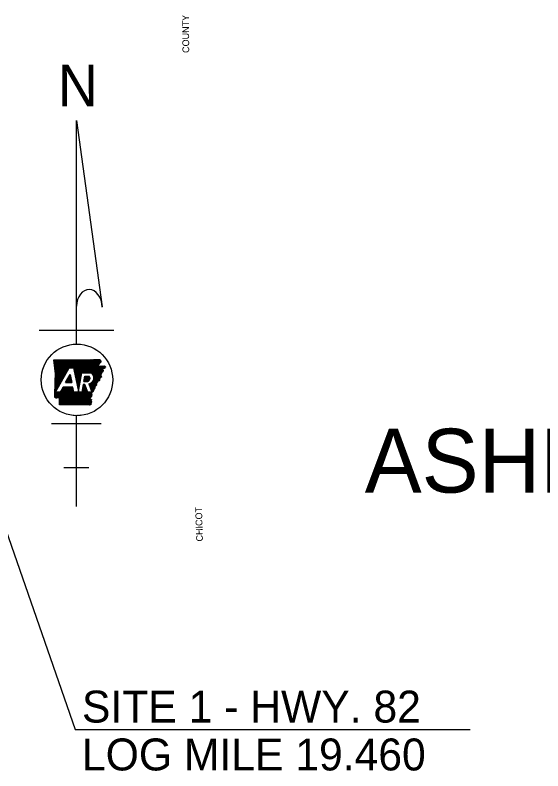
# Model space of a CAD drawing. Extents: x -2512 to 3792, y -435 to 2624.
# Drawn here: x 953 to 1350, y 1338 to 1907 of the extents above; entities that cross this region are included whole.
import ezdxf

# ---------------------------------------------------------------- set-up
doc = ezdxf.new("R2010")
doc.units = 0
for name, color, linetype in [('2', 7, 'Continuous'), ('Level 30', 7, 'Continuous'), ('R_Annotation', 7, 'Continuous'), ('R_Draft', 7, 'Continuous')]:
    doc.layers.add(name, color=color, linetype=linetype)

msp = doc.modelspace()

# ---------------------------------------------------------------- linework, layer by layer
at = {"layer": 'R_Annotation'}
for p, q in [((898.98, 1653.09), (997.83, 1369.55)), ((997.83, 1369.55), (1295.07, 1369.55))]:
    msp.add_line(p, q, dxfattribs=at)
at = {"layer": 'R_Draft'}
for p, q in [((998.69, 1827.36), (1018.1, 1687.13)), ((998.69, 1659.2), (998.69, 1827.36)), ((970.61, 1669.59), (1026.77, 1669.59)), ((981.66, 1647.15), (981.89, 1647.38)), ((981.74, 1646.49), (982.63, 1647.38)), ((981.82, 1645.83), (983.37, 1647.38)), ((981.9, 1645.17), (984.12, 1647.38)), ((981.99, 1644.5), (984.86, 1647.38)), ((982.07, 1643.84), (985.6, 1647.38)), ((982.15, 1643.18), (986.35, 1647.38)), ((982.23, 1642.52), (987.09, 1647.38)), ((982.31, 1641.86), (987.83, 1647.38)), ((982.4, 1641.2), (988.57, 1647.38)), ((982.48, 1640.54), (989.32, 1647.38)), ((982.56, 1639.88), (990.06, 1647.38)), ((982.64, 1639.22), (990.8, 1647.38)), ((982.73, 1638.56), (991.55, 1647.37)), ((982.75, 1631.15), (998.99, 1647.39)), ((982.78, 1631.92), (998.25, 1647.39)), ((982.8, 1632.69), (997.5, 1647.39)), ((982.81, 1637.89), (992.29, 1647.38)), ((982.83, 1633.45), (996.76, 1647.38)), ((982.85, 1634.22), (996.01, 1647.38)), ((982.88, 1634.99), (995.27, 1647.38)), ((982.89, 1637.23), (993.03, 1647.38)), ((982.9, 1635.76), (994.52, 1647.38)), ((982.93, 1636.53), (993.78, 1647.38)), ((993.79, 1641.44), (999.74, 1647.39)), ((994.53, 1641.44), (1000.48, 1647.39)), ((995.28, 1641.44), (1001.23, 1647.4)), ((996.02, 1641.44), (1001.99, 1647.41)), ((996.48, 1641.16), (1002.74, 1647.42)), ((996.61, 1640.55), (1003.5, 1647.43)), ((996.74, 1639.94), (1004.25, 1647.45)), ((996.88, 1639.33), (1005.01, 1647.46)), ((997.01, 1638.71), (1005.76, 1647.47)), ((997.14, 1638.1), (1006.52, 1647.48)), ((997.27, 1637.49), (1007.27, 1647.49)), ((997.4, 1636.88), (1008.03, 1647.5)), ((997.53, 1636.26), (1008.78, 1647.52)), ((997.66, 1635.65), (1009.54, 1647.53)), ((997.79, 1635.04), (1010.29, 1647.54)), ((997.92, 1634.43), (1011.05, 1647.55)), ((998.06, 1633.81), (1011.81, 1647.57)), ((998.19, 1633.2), (1012.57, 1647.58)), ((1003.35, 1637.62), (1013.33, 1647.6)), ((1004.09, 1637.62), (1014.09, 1647.62)), ((1004.84, 1637.62), (1014.85, 1647.64)), ((1005.58, 1637.62), (1015.61, 1647.65)), ((1006.32, 1637.62), (1016.37, 1647.67)), ((1007.07, 1637.62), (1016.54, 1647.09)), ((1007.81, 1637.62), (1016.9, 1646.71)), ((1008.55, 1637.62), (1016.99, 1646.06)), ((1009.3, 1637.62), (1015.3, 1643.62)), ((1009.97, 1637.55), (1015.15, 1642.73)), ((1010.38, 1637.22), (1015.93, 1642.77)), ((1010.74, 1636.84), (1016.72, 1642.81)), ((1011.06, 1636.41), (1017.5, 1642.85)), ((1011.34, 1635.95), (1018.28, 1642.89)), ((1011.56, 1635.43), (1019.07, 1642.93)), ((1011.74, 1634.86), (1019.77, 1642.9)), ((1011.84, 1634.22), (1020.12, 1642.5)), ((982.67, 1628.84), (990.82, 1636.98)), ((982.7, 1629.61), (991.79, 1638.7)), ((982.73, 1630.38), (992.76, 1640.41)), ((982.97, 1623.13), (993.34, 1641.44)), ((993.34, 1641.44), (996.42, 1641.44)), ((998.32, 1632.59), (1002.54, 1636.81)), ((1002.68, 1637.62), (1009.88, 1637.62)), ((1011.04, 1631.19), (1016.72, 1636.87)), ((1011.69, 1632.58), (1018.43, 1639.32)), ((1011.84, 1633.48), (1018.35, 1639.98)), ((1017.6, 1637.75), (1018.52, 1638.67)), ((1019.79, 1641.43), (1020.47, 1642.1)), ((982.6, 1626.53), (987.9, 1631.84)), ((982.62, 1627.3), (988.87, 1633.55)), ((982.65, 1628.07), (989.84, 1635.27)), ((990.6, 1630.32), (993.99, 1636.31)), ((990.64, 1630.32), (994.46, 1634.14)), ((991.38, 1630.32), (994.59, 1633.53)), ((991.52, 1631.95), (994.32, 1634.75)), ((992.12, 1630.32), (994.72, 1632.91)), ((992.49, 1633.66), (994.19, 1635.36)), ((992.87, 1630.32), (994.85, 1632.3)), ((993.46, 1635.38), (994.06, 1635.97)), ((993.61, 1630.32), (994.98, 1631.69)), ((994.35, 1630.32), (995.11, 1631.08)), ((998.45, 1631.98), (1002.38, 1635.91)), ((998.58, 1631.37), (1002.22, 1635.01)), ((998.71, 1630.75), (1002.06, 1634.11)), ((998.84, 1630.14), (1001.91, 1633.21)), ((998.97, 1629.53), (1001.75, 1632.31)), ((999.1, 1628.92), (1001.59, 1631.41)), ((1004.24, 1631.13), (1008.16, 1635.04)), ((1004.24, 1631.13), (1007.33, 1631.13)), ((1004.4, 1632.02), (1007.41, 1635.04)), ((1004.55, 1632.92), (1006.67, 1635.04)), ((1004.71, 1633.82), (1005.93, 1635.04)), ((1004.87, 1634.72), (1005.18, 1635.04)), ((1004.92, 1635.04), (1008.3, 1635.04)), ((1004.99, 1631.13), (1008.57, 1634.71)), ((1005.73, 1631.13), (1008.82, 1634.22)), ((1006.47, 1631.13), (1008.96, 1633.61)), ((1007.22, 1631.13), (1008.89, 1632.8)), ((1008.62, 1628.02), (1016.86, 1636.26)), ((1008.82, 1627.48), (1017, 1635.66)), ((1009.02, 1626.94), (1017.14, 1635.05)), ((1009.22, 1626.39), (1017.27, 1634.45)), ((1014.73, 1631.17), (1015.78, 1632.21)), ((982.52, 1624.23), (984.99, 1626.7)), ((982.55, 1625), (985.96, 1628.41)), ((982.57, 1625.77), (986.93, 1630.13)), ((982.66, 1619.16), (990.47, 1626.97)), ((983.1, 1618.86), (991.21, 1626.97)), ((983.63, 1618.65), (991.96, 1626.97)), ((984.52, 1618.79), (992.7, 1626.97)), ((985.27, 1618.8), (993.44, 1626.97)), ((985.85, 1618.64), (994.19, 1626.97)), ((985.88, 1617.18), (995.67, 1626.97)), ((985.88, 1617.92), (994.93, 1626.97)), ((985.88, 1616.44), (996.06, 1626.62)), ((985.88, 1615.7), (996.2, 1626.01)), ((985.89, 1614.96), (996.33, 1625.4)), ((988.71, 1626.97), (986.53, 1623.13)), ((987.37, 1624.62), (989.73, 1626.97)), ((988.34, 1626.33), (988.98, 1626.97)), ((995.99, 1626.97), (988.71, 1626.97)), ((990.6, 1630.32), (995.27, 1630.32)), ((993.32, 1613.47), (1006.11, 1626.26)), ((994.06, 1613.47), (1006.31, 1625.71)), ((995.1, 1630.32), (995.24, 1630.46)), ((999.23, 1628.3), (1001.44, 1630.51)), ((999.37, 1627.69), (1001.28, 1629.61)), ((999.5, 1627.08), (1001.12, 1628.71)), ((999.63, 1626.47), (1000.97, 1627.81)), ((999.76, 1625.85), (1000.81, 1626.91)), ((999.89, 1625.24), (1000.65, 1626.01)), ((1002.97, 1623.87), (1005.91, 1626.8)), ((1003.13, 1624.77), (1005.71, 1627.34)), ((1003.29, 1625.67), (1005.5, 1627.88)), ((1003.45, 1626.57), (1005.3, 1628.43)), ((1003.6, 1627.47), (1005.09, 1628.95)), ((1003.76, 1628.37), (1004.34, 1628.95)), ((1005.11, 1628.95), (1003.86, 1628.95)), ((1007.26, 1623.13), (1005.11, 1628.95)), ((1008.16, 1629.27), (1010.42, 1623.13)), ((1008.22, 1629.11), (1008.44, 1629.33)), ((1008.42, 1628.57), (1009.83, 1629.98)), ((1009.42, 1625.85), (1013.88, 1630.31)), ((1009.62, 1625.31), (1013.79, 1629.48)), ((1009.82, 1624.77), (1013.71, 1628.66)), ((1010.02, 1624.22), (1012.3, 1626.5)), ((1010.22, 1623.68), (1011.98, 1625.44)), ((982.38, 1619.63), (985.88, 1623.13)), ((982.39, 1620.38), (985.14, 1623.13)), ((982.42, 1621.15), (984.4, 1623.13)), ((982.45, 1621.92), (983.65, 1623.13)), ((982.47, 1622.69), (983.05, 1623.27)), ((982.5, 1623.46), (984.02, 1624.99)), ((986.53, 1623.13), (982.97, 1623.13)), ((985.89, 1614.21), (996.46, 1624.78)), ((985.9, 1613.48), (996.59, 1624.17)), ((986.64, 1613.48), (996.72, 1623.56)), ((987.38, 1613.48), (997.03, 1623.13)), ((988.13, 1613.48), (997.78, 1623.13)), ((988.87, 1613.48), (998.52, 1623.13)), ((989.61, 1613.48), (999.26, 1623.13)), ((990.35, 1613.48), (1000.01, 1623.13)), ((991.09, 1613.47), (1000.75, 1623.13)), ((991.84, 1613.47), (1001.49, 1623.13)), ((992.58, 1613.47), (1002.24, 1623.13)), ((994.81, 1613.47), (1006.51, 1625.17)), ((995.55, 1613.47), (1006.71, 1624.63)), ((996.29, 1613.47), (1006.91, 1624.08)), ((1002.85, 1623.13), (996.81, 1623.13)), ((997.03, 1613.46), (1007.11, 1623.54)), ((997.77, 1613.46), (1007.44, 1623.13)), ((998.52, 1613.46), (1008.18, 1623.13)), ((999.26, 1613.46), (1008.93, 1623.13)), ((1000, 1613.46), (1009.67, 1623.13)), ((1000.02, 1624.63), (1000.5, 1625.11)), ((1000.15, 1624.02), (1000.34, 1624.2)), ((1000.74, 1613.46), (1009.92, 1622.64)), ((1001.48, 1613.46), (1009.95, 1621.93)), ((1002.23, 1613.46), (1009.99, 1621.22)), ((1002.97, 1613.45), (1010.02, 1620.51)), ((1010.42, 1623.13), (1007.26, 1623.13)), ((1003.71, 1613.45), (1008.8, 1618.54)), ((1004.45, 1613.45), (1009.03, 1618.03)), ((1005.2, 1613.45), (1009.26, 1617.51)), ((1005.94, 1613.45), (1009.49, 1617)), ((1006.68, 1613.45), (1009.72, 1616.49)), ((1007.42, 1613.45), (1009.91, 1615.93)), ((1008.16, 1613.45), (1009.57, 1614.85)), ((1008.91, 1613.45), (1009.24, 1613.78)), ((998.69, 1537.15), (998.69, 1605.4)), ((979.97, 1599.6), (1017.41, 1599.6)), ((989.33, 1566.35), (1008.05, 1566.35))]:
    msp.add_line(p, q, dxfattribs=at)
for points in [[(981.63, 1647.38), (991.88, 1647.37), (1000.89, 1647.39), (1011.5, 1647.56), (1016.42, 1647.67)], [(981.63, 1647.38), (991.88, 1647.37), (1000.88, 1647.39), (1011.5, 1647.56), (1016.42, 1647.67)], [(982.76, 1631.44), (982.94, 1636.84), (981.63, 1647.38)], [(982.37, 1619.63), (982.94, 1636.84), (981.63, 1647.38)], [(1019.64, 1642.96), (1020.53, 1642.03), (1018.32, 1640.22), (1018.56, 1638.38), (1016.66, 1637.13), (1017.31, 1634.3), (1015.84, 1632.97), (1015.71, 1631.52), (1013.94, 1630.88), (1013.66, 1628.14), (1012.38, 1626.77), (1011.76, 1624.71), (1009.9, 1623.01), (1010.04, 1620), (1008.78, 1618.59), (1009.93, 1616.01), (1009.13, 1613.44)], [(1014.9, 1642.72), (1019.71, 1642.97)], [(1014.9, 1642.72), (1019.71, 1642.97)], [(996.42, 1641.44), (1000.24, 1623.62), (1002.68, 1637.62)], [(982.37, 1619.63), (982.76, 1631.44)], [(993.99, 1636.31), (995.27, 1630.32)], [(1004.24, 1631.13), (1004.92, 1635.04)], [(996.81, 1623.13), (995.99, 1626.97)], [(1003.86, 1628.95), (1002.85, 1623.13)], [(1009.13, 1613.44), (985.89, 1613.48), (985.88, 1618.61)], [(1009.13, 1613.44), (985.89, 1613.48), (985.88, 1618.61)]]:
    msp.add_lwpolyline(points, dxfattribs=at)
for centre, major_axis, ratio, start_param, end_param in [((1008.39, 1686.82), (-0.41, 13.48), 0.719778, 4.712385, 7.768526), ((1007.2, 1633.82), (-4.65, 0), 0.999987, 1.777838, 4.099264), ((1006.59, 1633.39), (-2.38, 0), 0.999987, 1.887169, 3.90762)]:
    msp.add_ellipse(centre, major_axis=major_axis, ratio=ratio, start_param=start_param, end_param=end_param, dxfattribs=at)
msp.add_ellipse((999.13, 1632.3), major_axis=(26.9, 0), ratio=0.999976, dxfattribs=at)
for points in [[(1016.42, 1647.67), (1016.45, 1647.39), (1016.54, 1647.25), (1016.55, 1646.98), (1016.66, 1646.86), (1016.85, 1646.75), (1017.01, 1646.57), (1017.05, 1646.36), (1016.99, 1646.13), (1016.98, 1645.88), (1016.96, 1645.67), (1016.92, 1645.47), (1016.77, 1645.31), (1016.62, 1645.2), (1016.49, 1645.07), (1016.4, 1644.93), (1016.23, 1644.78), (1016.06, 1644.61), (1015.93, 1644.48), (1015.8, 1644.3), (1015.73, 1644.1), (1015.59, 1643.96), (1015.47, 1643.83), (1015.32, 1643.66), (1015.25, 1643.5), (1015.1, 1643.3), (1015.07, 1643.11), (1014.98, 1642.96), (1014.97, 1642.93)], [(1016.42, 1647.67), (1016.45, 1647.39), (1016.54, 1647.25), (1016.55, 1646.98), (1016.66, 1646.87), (1016.84, 1646.75), (1017.01, 1646.57), (1017.05, 1646.35), (1017, 1646.13), (1016.98, 1645.88), (1016.96, 1645.67), (1016.92, 1645.47), (1016.77, 1645.31), (1016.62, 1645.2), (1016.49, 1645.07), (1016.39, 1644.93), (1016.23, 1644.77), (1016.06, 1644.62), (1015.93, 1644.48), (1015.8, 1644.3), (1015.73, 1644.1), (1015.59, 1643.96), (1015.47, 1643.84), (1015.32, 1643.66), (1015.25, 1643.49), (1015.1, 1643.3), (1015.07, 1643.11), (1014.97, 1642.95), (1014.97, 1642.93)], [(1019.64, 1642.96), (1019.71, 1642.97), (1019.93, 1642.74), (1020.02, 1642.55), (1020.16, 1642.44), (1020.32, 1642.39), (1020.44, 1642.24), (1020.52, 1642.08), (1020.48, 1641.94), (1020.3, 1641.93), (1020.1, 1641.9), (1019.91, 1641.9), (1019.76, 1641.77), (1019.9, 1641.6), (1020.09, 1641.44), (1020.14, 1641.27), (1020.03, 1641.11), (1019.83, 1641.02), (1019.63, 1640.94), (1019.46, 1640.79), (1019.37, 1640.64), (1019.18, 1640.58), (1018.98, 1640.52), (1018.8, 1640.51), (1018.6, 1640.47), (1018.4, 1640.37), (1018.32, 1640.21), (1018.34, 1639.98), (1018.34, 1639.73), (1018.54, 1639.64), (1018.73, 1639.64), (1018.91, 1639.54), (1018.89, 1639.4), (1018.75, 1639.22), (1018.6, 1639.09), (1018.44, 1639.02), (1018.29, 1638.88), (1018.34, 1638.75), (1018.47, 1638.66), (1018.57, 1638.52), (1018.56, 1638.38), (1018.4, 1638.29), (1018.24, 1638.33), (1018.12, 1638.48), (1017.98, 1638.53), (1017.86, 1638.59), (1017.72, 1638.51), (1017.72, 1638.33), (1017.67, 1638.13), (1017.71, 1637.98), (1017.77, 1637.78), (1017.76, 1637.63), (1017.71, 1637.41), (1017.6, 1637.19), (1017.48, 1637.12), (1017.42, 1637.36), (1017.4, 1637.56), (1017.32, 1637.67), (1017.22, 1637.68), (1017.09, 1637.58), (1016.95, 1637.44), (1016.76, 1637.28), (1016.65, 1637.12), (1016.71, 1636.92), (1016.85, 1636.88), (1016.96, 1636.91), (1017.02, 1637.04), (1017.12, 1637.05), (1017.22, 1636.86)], [(1017.22, 1636.86), (1017.25, 1636.68), (1017.14, 1636.48), (1017.1, 1636.28), (1017.12, 1636.08), (1016.92, 1635.98), (1016.74, 1635.85), (1016.85, 1635.7), (1017.04, 1635.56), (1017.22, 1635.45), (1017.34, 1635.34), (1017.38, 1635.09), (1017.41, 1634.92), (1017.47, 1634.69), (1017.5, 1634.53), (1017.38, 1634.34), (1017.25, 1634.3), (1017.11, 1634.35), (1016.95, 1634.36), (1016.81, 1634.24), (1016.72, 1634.06), (1016.62, 1633.88), (1016.55, 1633.73), (1016.48, 1633.56), (1016.34, 1633.37), (1016.17, 1633.34), (1015.97, 1633.29), (1015.85, 1633.15), (1015.87, 1632.91), (1015.98, 1632.76), (1016.07, 1632.56), (1016.13, 1632.39), (1016.1, 1632.17), (1016.02, 1632.01), (1015.9, 1631.92), (1015.85, 1631.72), (1015.76, 1631.56), (1015.69, 1631.51), (1015.54, 1631.53), (1015.37, 1631.56), (1015.23, 1631.54), (1015.1, 1631.48), (1014.97, 1631.52), (1014.83, 1631.67), (1014.71, 1631.79), (1014.58, 1631.83), (1014.45, 1631.76), (1014.43, 1631.55), (1014.49, 1631.34), (1014.55, 1631.05), (1014.49, 1630.87), (1014.47, 1630.57)], [(1014.47, 1630.57), (1014.25, 1630.41), (1014.15, 1630.23), (1013.59, 1630.28), (1013.6, 1630.08), (1013.4, 1629.98), (1013.22, 1629.85), (1013.32, 1629.7), (1013.52, 1629.56), (1013.71, 1629.45), (1013.83, 1629.34), (1013.86, 1629.08), (1013.89, 1628.92), (1013.95, 1628.69), (1013.98, 1628.53), (1013.86, 1628.34), (1013.73, 1628.3), (1013.59, 1628.35), (1013.43, 1628.36), (1013.3, 1628.23), (1013.2, 1628.06), (1013.11, 1627.87), (1013.03, 1627.72), (1012.96, 1627.56), (1012.83, 1627.37), (1012.66, 1627.34), (1012.45, 1627.29), (1012.33, 1627.15), (1012.35, 1626.91), (1012.46, 1626.76), (1012.55, 1626.56), (1012.61, 1626.39), (1012.59, 1626.17), (1012.5, 1626.01), (1012.38, 1625.91), (1012.33, 1625.71), (1012.25, 1625.56), (1012.17, 1625.51), (1012.02, 1625.53), (1011.86, 1625.56), (1011.72, 1625.54), (1011.59, 1625.47), (1011.45, 1625.52), (1011.31, 1625.67), (1011.2, 1625.78), (1011.07, 1625.83), (1010.93, 1625.76), (1010.91, 1625.55), (1010.98, 1625.34), (1011.03, 1625.04), (1010.98, 1624.87), (1010.96, 1624.57)], [(985.88, 1618.61), (985.9, 1618.6), (985.78, 1618.68), (985.62, 1618.76), (985.43, 1618.78), (985.2, 1618.81), (985, 1618.83), (984.8, 1618.96), (984.59, 1618.83), (984.34, 1618.72), (984.2, 1618.84), (984.02, 1618.76), (983.89, 1618.8), (983.67, 1618.64), (983.46, 1618.7), (983.31, 1618.66), (983.12, 1618.66), (983.08, 1618.88), (982.89, 1618.91), (982.74, 1619), (982.63, 1619.22), (982.55, 1619.4), (982.37, 1619.63)], [(985.88, 1618.61), (985.9, 1618.6), (985.78, 1618.68), (985.62, 1618.77), (985.43, 1618.78), (985.2, 1618.81), (985, 1618.83), (984.8, 1618.96), (984.58, 1618.82), (984.34, 1618.72), (984.2, 1618.84), (984.02, 1618.76), (983.89, 1618.8), (983.67, 1618.65), (983.46, 1618.7), (983.31, 1618.66), (983.12, 1618.66), (983.08, 1618.88), (982.9, 1618.91), (982.74, 1619), (982.63, 1619.22), (982.55, 1619.39), (982.37, 1619.63)], [(1010.1, 1622.18), (1010.04, 1622.04), (1009.97, 1621.78), (1009.99, 1621.57), (1010.09, 1621.39), (1010.23, 1621.29), (1010.4, 1621.14), (1010.39, 1620.92), (1010.29, 1620.84), (1010.07, 1620.89), (1009.9, 1620.97), (1009.75, 1620.92), (1009.56, 1620.83), (1009.41, 1620.8), (1009.42, 1620.5), (1009.61, 1620.29), (1009.78, 1620.29), (1009.98, 1620.26), (1010.05, 1620.03), (1009.94, 1619.84), (1009.75, 1619.75), (1009.51, 1619.87), (1009.34, 1619.98), (1009.17, 1620.1), (1008.95, 1620.15), (1008.83, 1620.13), (1008.77, 1619.87), (1008.87, 1619.62), (1009.04, 1619.46), (1009.19, 1619.24), (1009.17, 1619.08), (1009.05, 1619.04), (1008.85, 1618.99), (1008.73, 1618.93), (1008.7, 1618.88), (1008.76, 1618.66), (1008.81, 1618.43), (1008.81, 1618.25), (1008.74, 1618.09), (1008.64, 1617.84), (1008.65, 1617.67), (1008.73, 1617.59), (1008.82, 1617.62), (1008.95, 1617.71), (1009.03, 1617.81), (1009.1, 1617.94), (1009.23, 1618.04), (1009.4, 1617.95), (1009.44, 1617.75), (1009.34, 1617.58), (1009.21, 1617.5), (1009.05, 1617.44), (1008.92, 1617.3), (1008.95, 1617.13), (1009.05, 1617.05), (1009.29, 1617.09), (1009.44, 1617.16), (1009.53, 1617.25), (1009.64, 1617.36), (1009.69, 1617.47), (1009.78, 1617.58), (1009.93, 1617.61), (1010, 1617.52), (1009.97, 1617.3), (1009.88, 1617.1), (1009.76, 1616.93), (1009.63, 1616.81), (1009.46, 1616.55), (1009.49, 1616.31), (1009.56, 1616.1), (1009.64, 1615.96), (1009.8, 1615.99), (1009.97, 1616.01), (1010.07, 1615.93), (1010.06, 1615.75), (1009.93, 1615.57), (1009.81, 1615.41), (1009.75, 1615.18), (1009.77, 1615.02), (1009.77, 1614.88), (1009.72, 1614.72), (1009.64, 1614.63), (1009.4, 1614.63), (1009.15, 1614.66), (1009.02, 1614.59), (1009.05, 1614.37), (1009.19, 1614.21), (1009.29, 1614.13), (1009.44, 1613.95), (1009.5, 1613.81), (1009.48, 1613.68), (1009.39, 1613.57), (1009.13, 1613.44)], [(1010.1, 1622.18), (1010.04, 1622.04), (1009.97, 1621.78), (1009.99, 1621.57), (1010.09, 1621.39), (1010.23, 1621.29), (1010.4, 1621.14), (1010.39, 1620.92), (1010.29, 1620.84), (1010.07, 1620.89), (1009.9, 1620.97), (1009.75, 1620.92), (1009.56, 1620.83), (1009.41, 1620.8), (1009.42, 1620.5), (1009.61, 1620.29), (1009.78, 1620.29), (1009.98, 1620.26), (1010.05, 1620.03), (1009.94, 1619.84), (1009.75, 1619.75), (1009.51, 1619.87), (1009.34, 1619.98), (1009.17, 1620.1), (1008.95, 1620.15), (1008.83, 1620.13), (1008.77, 1619.87), (1008.87, 1619.62), (1009.04, 1619.46), (1009.19, 1619.24), (1009.17, 1619.08), (1009.05, 1619.04), (1008.85, 1618.99), (1008.73, 1618.93), (1008.7, 1618.88), (1008.76, 1618.66), (1008.81, 1618.43), (1008.81, 1618.25), (1008.74, 1618.09), (1008.64, 1617.84), (1008.65, 1617.67), (1008.73, 1617.59), (1008.82, 1617.62), (1008.95, 1617.71), (1009.03, 1617.81), (1009.1, 1617.94), (1009.23, 1618.04), (1009.4, 1617.95), (1009.44, 1617.75), (1009.34, 1617.58), (1009.21, 1617.5), (1009.05, 1617.44), (1008.92, 1617.3), (1008.95, 1617.13), (1009.05, 1617.05), (1009.29, 1617.09), (1009.44, 1617.16), (1009.53, 1617.25), (1009.64, 1617.36), (1009.69, 1617.47), (1009.78, 1617.58), (1009.93, 1617.61), (1010, 1617.52), (1009.97, 1617.3), (1009.88, 1617.1), (1009.76, 1616.93), (1009.63, 1616.81), (1009.46, 1616.55), (1009.49, 1616.31), (1009.56, 1616.1), (1009.64, 1615.96), (1009.8, 1615.99), (1009.97, 1616.01), (1010.07, 1615.93), (1010.06, 1615.75), (1009.93, 1615.57), (1009.81, 1615.41), (1009.75, 1615.18), (1009.77, 1615.02), (1009.77, 1614.88), (1009.72, 1614.72), (1009.64, 1614.63), (1009.4, 1614.63), (1009.15, 1614.66), (1009.02, 1614.59), (1009.05, 1614.37), (1009.19, 1614.21), (1009.29, 1614.13), (1009.44, 1613.95), (1009.5, 1613.81), (1009.48, 1613.68), (1009.39, 1613.57), (1009.13, 1613.44)], [(1010.96, 1624.57), (1010.94, 1624.56), (1010.83, 1624.42), (1010.89, 1624.19), (1011.14, 1624.11), (1011.25, 1623.89), (1011.26, 1623.7), (1011.18, 1623.44), (1011.06, 1623.32), (1010.84, 1623.27), (1010.67, 1623.24), (1010.64, 1622.95), (1010.57, 1622.8), (1010.43, 1622.76), (1010.24, 1622.85), (1010.13, 1622.9), (1009.99, 1622.96), (1009.81, 1623.06), (1009.68, 1623.04), (1009.71, 1622.77), (1009.73, 1622.76), (1009.88, 1622.55), (1010.03, 1622.38), (1010.1, 1622.18)], [(1010.96, 1624.57), (1010.94, 1624.56), (1010.83, 1624.42), (1010.89, 1624.19), (1011.14, 1624.11), (1011.25, 1623.89), (1011.26, 1623.7), (1011.18, 1623.44), (1011.06, 1623.32), (1010.84, 1623.27), (1010.67, 1623.24), (1010.64, 1622.95), (1010.57, 1622.8), (1010.43, 1622.76), (1010.24, 1622.85), (1010.13, 1622.9), (1009.99, 1622.96), (1009.81, 1623.06), (1009.68, 1623.04), (1009.71, 1622.77), (1009.73, 1622.76), (1009.88, 1622.55), (1010.03, 1622.38), (1010.1, 1622.18)]]:
    msp.add_spline(points, degree=3, dxfattribs=at)

# ---------------------------------------------------------------- texts
at = {"layer": '2'}
msp.add_text('ASHLEY,  DREW & JEFFERSON COUNTIES', height=48, dxfattribs=at).set_placement((1215.69, 1547.59))
at = {"layer": 'Level 30'}
for s, rotation, p in [('COUNTY', 90.4678, (1083.59, 1878.17)), ('CHICOT', 91.5527, (1093.88, 1510.88))]:
    msp.add_text(s, height=5.069, rotation=rotation, dxfattribs=at).set_placement(p)
at = {"layer": 'R_Annotation'}
for s, p in [('SITE 1 - HWY. 82', (1002.89, 1374.67)), ('LOG MILE 19.460', (1002.89, 1338.67))]:
    msp.add_text(s, height=24, dxfattribs=at).set_placement(p)
at = {"layer": 'R_Draft'}
for s, height, p in [('N', 31.3, (984.74, 1837.95)), ('STS 10-03-17', 0.7778, (996.56, 1605.62))]:
    msp.add_text(s, height=height, dxfattribs=at).set_placement(p)

doc.saveas('drawing.dxf')
